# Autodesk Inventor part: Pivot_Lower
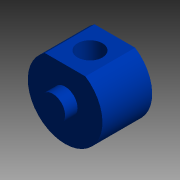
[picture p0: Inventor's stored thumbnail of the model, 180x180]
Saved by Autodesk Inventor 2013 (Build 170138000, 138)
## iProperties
Shininess: 0.0
Length Units: 11272
Angle Units: 11279
Time Units: 11290
Mass Units: 11283
Length Display Precision: 2
Angle Display Precision: 1
Compacted: True
Created: 1999-05
Part Number: Pivot_Lower
Document SubType Name: Modeling
Designer: Administrator
Density: 7.85 g/cm^3
Material: Steel
Mass: 22.7912 g
Surface Area: 17.5632 cm^2
Volume: 2.90333 cm^3
Density: 0.0
Volumn: 0.0
Area: 0.0
PropertySet Name: Model Information
Control State: 0
Master: False
Checked Out: False
Author: Administrator
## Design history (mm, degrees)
node "y-z Plane"
  node "x-z Plane"
  node "x-y Plane"
node "Extrusion1" dims "d1" = 12.7, "d2" = 0
  sketch "Sketch1"
    geometry: C1 r 9.525 at (0, 0); 1 further point
    constraints: 1 centre point, 1 coincident
    dimensions: "d0" = 19.05 diameter of C1
node "Extrusion2" dims "d4" = 19.05, "d5" = 0
  sketch "Sketch2"
    geometry: L1 (-5.168, 8.001)-(5.168, 8.001); A1 r 9.525 centre (0, 0) between (-5.168, 8.001) and (5.168, 8.001) reference
    constraints: 2 end point, 2 point on circle, 1 horizontal
    dimensions: "d3" = 17.526 dimension on A1 L1
node "Extrusion3" dims "d7" = 3.175, "d8" = 0
  sketch "Sketch3"
    geometry: C1 r 3.175 at (0, 0); A1 r 9.525 centre (0, 0) between (-5.168, 8.001) and (5.168, 8.001) reference
    constraints: 1 centre point
    dimensions: "d6" = 6.35 diameter of C1
node "Extrusion4" dims "d10" = 3.175, "d11" = 0
  sketch "Sketch4"
    geometry: C1 r 3.175 at (0, 0); A1 r 9.525 centre (0, 0) between (-5.168, 8.001) and (5.168, 8.001) reference
    constraints: 1 centre point
    dimensions: "d9" = 6.34968 diameter of C1
workplane "Work Plane1"
node "Hole1" dims "d14" = 6.35, "d15" = 9.525, "d16" = 6.35, "d17" = 60 deg, "d18" = 19.05, "d19" = 118 deg
  sketch "Sketch5"
    geometry: 2 further points
    constraints: 1 coincident
body "Solid1"
